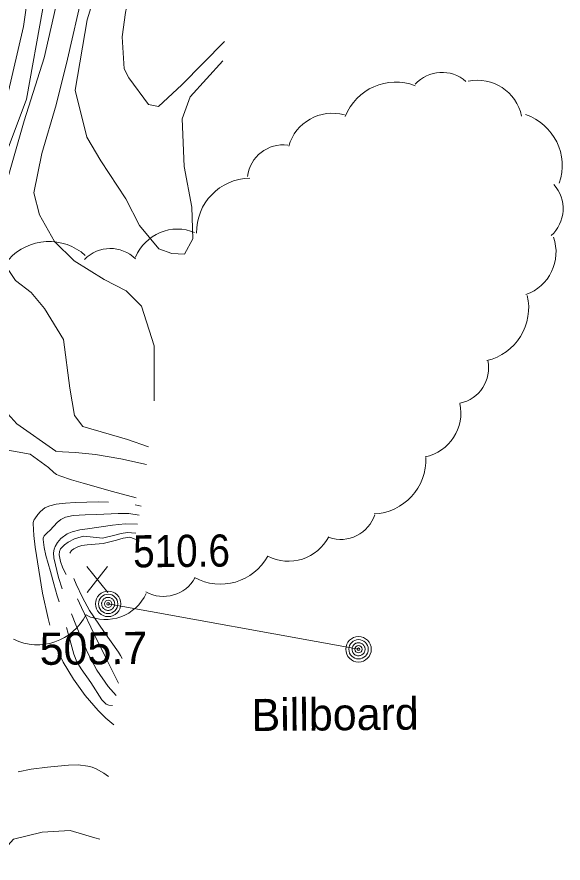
# Model space of a CAD drawing. Extents: x 2361284 to 2366480, y 6976556 to 6985346.
# Drawn here: x 2364716.6 to 2364798.2, y 6978408.5 to 6978534.7 of the extents above; entities that cross this region are included whole.
import ezdxf

# ---------------------------------------------------------------- set-up
doc = ezdxf.new("R2010")
doc.units = 0
doc.header["$LTSCALE"] = 1.9
for name, color, linetype, lineweight in [('11', 7, 'Continuous', 13), ('12', 7, 'Continuous', 13), ('13', 7, 'Continuous', 13), ('16', 7, 'Continuous', 13), ('20', 7, 'Continuous', 13), ('22', 7, 'Continuous', 13), ('4', 7, 'Continuous', 13)]:
    doc.layers.add(name, color=color, linetype=linetype, lineweight=lineweight)

msp = doc.modelspace()

# ---------------------------------------------------------------- linework, layer by layer
at = {"layer": '11'}
msp.add_line((2364767.64, 6978440.362), (2364730.263, 6978447.136), dxfattribs=at)
at = {"layer": '12'}
for p, q in [((2364730.202, 6978448.849), (2364727.085, 6978452.7)), ((2364727.122, 6978448.82), (2364730.165, 6978452.729))]:
    msp.add_line(p, q, dxfattribs=at)
for points in [[(2364750.359, 6978632.669), (2364748.604, 6978629.042), (2364742.684, 6978613.334), (2364736.777, 6978599.207), (2364731.034, 6978581.641), (2364723.423, 6978559.607), (2364719.142, 6978543.817), (2364717.643, 6978533.281), (2364713.596, 6978516.152), (2364707.687, 6978496.026), (2364707.136, 6978484.479), (2364708.384, 6978478.43), (2364710.15, 6978472.516), (2364714.733, 6978470.18), (2364718.619, 6978469.487), (2364721.379, 6978467.494)], [(2364744.069, 6978574.975), (2364740.975, 6978564.775), (2364736.359, 6978548.471), (2364733.744, 6978539.585), (2364732.854, 6978535.386), (2364732.338, 6978531.741), (2364732.664, 6978526.975), (2364733.366, 6978525.641), (2364736.304, 6978521.639), (2364737.777, 6978521.363), (2364741.247, 6978524.596), (2364747.606, 6978531.046)]]:
    msp.add_lwpolyline(points, dxfattribs=at)
at = {"layer": '13'}
for points in [[(2364752.059, 6978630.645), (2364748.887, 6978623.483), (2364744.822, 6978611.455), (2364740.85, 6978598.896), (2364733.997, 6978583.46), (2364728.05, 6978566.202), (2364723.391, 6978550.377), (2364720.497, 6978535.998), (2364718.096, 6978522.456), (2364713.324, 6978509.969), (2364711.568, 6978503.302), (2364710.216, 6978498.26), (2364709.669, 6978494.723), (2364710.081, 6978492.397), (2364711.554, 6978486.861), (2364712.256, 6978483.538), (2364713.878, 6978476.983), (2364716.627, 6978473.979), (2364722.436, 6978469.904)], [(2364740.908, 6978574.955), (2364740.363, 6978573.32), (2364735.089, 6978558.978), (2364730.529, 6978545.375), (2364727.134, 6978534.261), (2364725.363, 6978523.795), (2364727.07, 6978516.78), (2364729.194, 6978513.23), (2364732.918, 6978507.585), (2364734.946, 6978503.594), (2364737.819, 6978500.121), (2364739.786, 6978499.401), (2364741.637, 6978499.299), (2364742.915, 6978501.63), (2364742.741, 6978506.338), (2364741.623, 6978512.378), (2364741.295, 6978519.506), (2364742.52, 6978522.772), (2364747.363, 6978528.183)], [(2364726.436, 6978538.225), (2364724.2, 6978528.403), (2364722.514, 6978521.578), (2364720.342, 6978514.346), (2364719.148, 6978508.454), (2364720.009, 6978505.172), (2364722.268, 6978501.213), (2364725.205, 6978498.342), (2364729.672, 6978495.525), (2364732.928, 6978493.855), (2364735.23, 6978491.556), (2364737.107, 6978485.654), (2364737.155, 6978477.454)], [(2364722.387, 6978536.026), (2364720.717, 6978528.62), (2364717.737, 6978519.192), (2364715.249, 6978510.497), (2364714.431, 6978507.179), (2364713.441, 6978503.01), (2364714.618, 6978498.072), (2364716.423, 6978495.409), (2364718.75, 6978493.58), (2364720.783, 6978491.209), (2364723.607, 6978486.586), (2364724.546, 6978479.324), (2364725.251, 6978475.222), (2364726.471, 6978473.592), (2364733.129, 6978471.664), (2364736.29, 6978470.545)], [(2364728.996, 6978412.023), (2364728.264, 6978412.246), (2364724.604, 6978413.342), (2364720.426, 6978413.062), (2364716.146, 6978412.021), (2364714.145, 6978409.782), (2364712.098, 6978404.431), (2364709.934, 6978397.481), (2364707.365, 6978390.986), (2364702.271, 6978384.017), (2364696.655, 6978375.143), (2364695.702, 6978372.639), (2364695.939, 6978367.306), (2364699.956, 6978361.393), (2364705.109, 6978357.943), (2364707.713, 6978355.528), (2364708.332, 6978354.553), (2364710.337, 6978352.952), (2364707.952, 6978350.35), (2364703.557, 6978348.688), (2364701.789, 6978346.451), (2364699.834, 6978343.551), (2364700.077, 6978342.414), (2364702.588, 6978341.288)]]:
    msp.add_lwpolyline(points, dxfattribs=at)
at = {"layer": '16'}
for centre, radius, start, end in [((2364780.076, 6978521.069), 5.381, 48.10943, 138.10943), ((2364773.188, 6978516.923), 8.076, 68.82502, 158.82502), ((2364785.38, 6978518.548), 6.734, 11.77598, 101.77598), ((2364763.708, 6978513.608), 6.734, 74.37675, 164.37675), ((2364789.968, 6978512.504), 8.076, 341.1653, 71.1653), ((2364756.41, 6978510.257), 5.381, 82.90169, 172.90169), ((2364751.536, 6978502.59), 8.076, 91.03314, 181.03314), ((2364792.791, 6978506.088), 5.381, 312.01795, 42.01795), ((2364740.595, 6978496.326), 6.734, 67.5884, 157.5884), ((2364790.387, 6978499.647), 6.734, 289.2099, 19.2099), ((2364721.427, 6978493.139), 8.076, 47.96859, 137.96859), ((2364730.585, 6978494.779), 5.381, 45.64299, 135.64299), ((2364784.964, 6978491.31), 8.076, 283.21455, 13.21455), ((2364781.664, 6978482.337), 5.381, 281.98727, 11.98727), ((2364776.185, 6978475.652), 6.734, 281.98727, 11.98727), ((2364769.598, 6978468.624), 8.076, 272.63358, 2.63358), ((2364764.967, 6978462.133), 5.381, 251.57895, 341.57895), ((2364757.204, 6978460.231), 6.734, 242.72757, 332.72757), ((2364747.038, 6978458.16), 8.076, 241.08099, 331.08099), ((2364738.511, 6978453.631), 5.381, 241.08099, 331.08099), ((2364729.854, 6978451.537), 6.734, 245.03229, 335.03229), ((2364719.702, 6978449.102), 8.076, 243.95518, 333.95518)]:
    msp.add_arc(centre, radius, start, end, dxfattribs=at)
at = {"layer": '20'}
msp.add_line((2364734.282, 6978461.916), (2364735.194, 6978461.695), dxfattribs=at)
for points in [[(2364722.456, 6978469.864), (2364725.408, 6978469.722), (2364728.351, 6978469.42), (2364732.177, 6978468.796), (2364735.965, 6978467.942)], [(2364721.582, 6978443.963), (2364721.303, 6978444.941), (2364720.477, 6978448.733), (2364719.893, 6978452.149), (2364719.372, 6978455.574), (2364719.165, 6978457.342), (2364719.058, 6978459.111), (2364719.076, 6978459.301), (2364719.105, 6978459.432), (2364719.183, 6978459.632), (2364719.301, 6978459.833), (2364719.764, 6978460.488), (2364720.15, 6978460.922), (2364720.806, 6978461.448), (2364721.174, 6978461.641), (2364721.573, 6978461.785), (2364722.511, 6978462.004), (2364723.919, 6978462.177), (2364725.329, 6978462.251), (2364728.828, 6978462.354), (2364730.318, 6978462.308)], [(2364722.929, 6978447.426), (2364722.661, 6978448.334), (2364722.154, 6978450.139), (2364721.656, 6978451.945), (2364720.974, 6978454.339), (2364720.702, 6978455.537), (2364720.541, 6978456.725), (2364720.559, 6978456.935), (2364720.716, 6978457.267), (2364721.141, 6978457.721), (2364721.607, 6978458.155), (2364722.647, 6978459.285), (2364723.212, 6978459.751), (2364723.879, 6978460.067), (2364725.047, 6978460.328), (2364726.816, 6978460.445), (2364728.586, 6978460.472), (2364731.744, 6978460.642), (2364733.325, 6978460.607), (2364734.897, 6978460.352)], [(2364723.411, 6978449.381), (2364722.855, 6978451.077), (2364722.157, 6978454.01), (2364722.12, 6978454.74), (2364722.215, 6978455.291), (2364722.361, 6978455.692), (2364722.705, 6978456.296), (2364723.2, 6978456.87), (2364724.153, 6978457.599), (2364724.89, 6978457.906), (2364726.017, 6978458.167), (2364727.186, 6978458.328), (2364730.911, 6978458.904), (2364732.779, 6978459.062), (2364734.64, 6978459.019)], [(2364723.971, 6978451.497), (2364723.501, 6978452.473), (2364723.132, 6978453.48), (2364722.932, 6978454.478), (2364722.988, 6978454.948), (2364723.164, 6978455.34), (2364723.728, 6978455.955), (2364724.295, 6978456.351), (2364725.26, 6978456.83), (2364726.217, 6978457.159), (2364726.616, 6978457.223), (2364729.409, 6978456.949), (2364731.265, 6978457.407), (2364732.203, 6978457.646), (2364733.142, 6978457.765), (2364733.762, 6978457.731), (2364734.382, 6978457.697)], [(2364731.785, 6978435.281), (2364731.642, 6978435.58), (2364731.49, 6978435.878), (2364729.797, 6978439.292), (2364728.114, 6978442.716), (2364726.268, 6978446.588), (2364725.665, 6978447.872)], [(2364731.473, 6978433.448), (2364730.24, 6978434.816), (2364728.557, 6978437.23), (2364727.181, 6978439.877), (2364725.432, 6978443.99), (2364724.797, 6978445.634)], [(2364730.897, 6978431.982), (2364730.366, 6978431.997), (2364729.945, 6978432.183), (2364729.299, 6978432.797), (2364727.664, 6978435.412), (2364726.214, 6978437.458), (2364725.604, 6978438.512), (2364725.143, 6978439.648), (2364724.543, 6978441.822), (2364724.056, 6978443.587)], [(2364731.124, 6978429.064), (2364729.894, 6978430.103), (2364728.764, 6978431.232), (2364726.832, 6978433.474), (2364725.079, 6978435.877), (2364723.545, 6978438.453), (2364722.912, 6978439.797), (2364722.779, 6978440.146)]]:
    msp.add_lwpolyline(points, dxfattribs=at)
at = {"layer": '22'}
for points in [[(2364721.379, 6978467.494), (2364722.146, 6978466.751), (2364722.559, 6978466.445), (2364723.031, 6978466.219), (2364724.776, 6978465.666), (2364726.531, 6978465.162), (2364730.913, 6978463.924), (2364734.462, 6978462.948)], [(2364724.52, 6978454.723), (2364724.807, 6978455.076), (2364725.134, 6978455.339), (2364725.712, 6978455.634), (2364726.32, 6978455.83), (2364727.119, 6978455.958), (2364729.517, 6978456.13), (2364731.512, 6978456.649), (2364732.51, 6978456.919), (2364733.498, 6978457.068), (2364733.618, 6978457.059), (2364733.819, 6978456.991), (2364734.13, 6978456.844), (2364734.281, 6978456.776), (2364734.441, 6978456.747)], [(2364732.37, 6978438.987), (2364732.086, 6978439.454), (2364731.791, 6978439.911), (2364729.642, 6978443.021), (2364727.472, 6978446.129), (2364726.423, 6978448.08), (2364725.504, 6978450.101), (2364725.136, 6978450.927)], [(2364730.337, 6978421.386), (2364729.612, 6978421.899), (2364728.476, 6978422.528), (2364727.864, 6978422.762), (2364727.232, 6978422.936), (2364725.781, 6978423.122), (2364724.341, 6978423.089), (2364722.772, 6978422.944), (2364721.214, 6978422.769), (2364718.776, 6978422.476), (2364716.81, 6978422.097)]]:
    msp.add_lwpolyline(points, dxfattribs=at)
at = {"layer": '4'}
for centre, radius in [((2364730.263, 6978447.136), 1.9), ((2364730.263, 6978447.136), 1.442), ((2364730.263, 6978447.136), 0.539), ((2364730.263, 6978447.136), 0.192), ((2364767.64, 6978440.362), 1.9), ((2364767.64, 6978440.362), 1.442), ((2364767.64, 6978440.362), 0.539), ((2364767.64, 6978440.362), 0.192)]:
    msp.add_circle(centre, radius, dxfattribs=at)
for centre, start, end in [((2364730.263, 6978447.136), 175.14463, 186.39466), ((2364730.263, 6978447.136), 163.89671, 175.14675), ((2364730.263, 6978447.136), 186.39597, 197.64601), ((2364730.263, 6978447.136), 152.64729, 163.89733), ((2364730.263, 6978447.136), 141.39537, 152.6454), ((2364730.263, 6978447.136), 130.14764, 141.39767), ((2364730.263, 6978447.136), 118.89707, 130.14711), ((2364730.263, 6978447.136), 107.64524, 118.89528), ((2364730.263, 6978447.136), 96.39711, 107.64715), ((2364730.263, 6978447.136), 85.147, 96.39703), ((2364730.263, 6978447.136), 73.89671, 85.14675), ((2364730.263, 6978447.136), 62.64376, 73.89379), ((2364730.263, 6978447.136), 51.3993, 62.64933), ((2364730.263, 6978447.136), 40.14515, 51.39518), ((2364730.263, 6978447.136), 28.89494, 40.14497), ((2364730.263, 6978447.136), 17.6494, 28.89944), ((2364730.263, 6978447.136), 6.39598, 17.64601), ((2364730.263, 6978447.136), 343.8967, 355.14674), ((2364730.263, 6978447.136), 355.14405, 6.39409), ((2364730.263, 6978447.136), 197.64774, 208.89778), ((2364730.263, 6978447.136), 208.89706, 220.14709), ((2364730.263, 6978447.136), 220.14515, 231.39518), ((2364730.263, 6978447.136), 231.39653, 242.64656), ((2364730.263, 6978447.136), 242.6467, 253.89673), ((2364730.263, 6978447.136), 253.89671, 265.14675), ((2364730.263, 6978447.136), 265.147, 276.39703), ((2364730.263, 6978447.136), 276.39711, 287.64715), ((2364730.263, 6978447.136), 287.64524, 298.89527), ((2364730.263, 6978447.136), 298.89494, 310.14497), ((2364730.263, 6978447.136), 310.14764, 321.39767), ((2364730.263, 6978447.136), 321.39653, 332.64656), ((2364730.263, 6978447.136), 332.64729, 343.89733), ((2364767.64, 6978440.362), 152.64729, 163.89733), ((2364767.64, 6978440.362), 141.39537, 152.6454), ((2364767.64, 6978440.362), 130.14764, 141.39767), ((2364767.64, 6978440.362), 118.89707, 130.14711), ((2364767.64, 6978440.362), 107.64524, 118.89528), ((2364767.64, 6978440.362), 96.39711, 107.64715), ((2364767.64, 6978440.362), 85.147, 96.39703), ((2364767.64, 6978440.362), 73.89671, 85.14675), ((2364767.64, 6978440.362), 62.64376, 73.89379), ((2364767.64, 6978440.362), 51.3993, 62.64933), ((2364767.64, 6978440.362), 40.14515, 51.39518), ((2364767.64, 6978440.362), 28.89494, 40.14497), ((2364767.64, 6978440.362), 17.6494, 28.89944), ((2364767.64, 6978440.362), 175.14463, 186.39466), ((2364767.64, 6978440.362), 163.89671, 175.14675), ((2364767.64, 6978440.362), 186.39597, 197.64601), ((2364767.64, 6978440.362), 197.64774, 208.89778), ((2364767.64, 6978440.362), 208.89706, 220.14709), ((2364767.64, 6978440.362), 220.14515, 231.39518), ((2364767.64, 6978440.362), 231.39653, 242.64656), ((2364767.64, 6978440.362), 242.6467, 253.89673), ((2364767.64, 6978440.362), 287.64524, 298.89527), ((2364767.64, 6978440.362), 298.89494, 310.14497), ((2364767.64, 6978440.362), 310.14764, 321.39767), ((2364767.64, 6978440.362), 321.39653, 332.64656), ((2364767.64, 6978440.362), 332.64729, 343.89733), ((2364767.64, 6978440.362), 6.39598, 17.64601), ((2364767.64, 6978440.362), 343.8967, 355.14674), ((2364767.64, 6978440.362), 355.14405, 6.39409), ((2364767.64, 6978440.362), 253.89671, 265.14675), ((2364767.64, 6978440.362), 265.147, 276.39703), ((2364767.64, 6978440.362), 276.39711, 287.64715)]:
    msp.add_arc(centre, 0.973, start, end, dxfattribs=at)

# ---------------------------------------------------------------- texts
at = {"layer": '11'}
msp.add_text('Billboard', height=4.799, rotation=0.545, dxfattribs=at).set_placement((2364751.684, 6978428.149))
at = {"layer": '12', "width": 0.9}
msp.add_text('510.6', height=4.799, rotation=0.545, dxfattribs=at).set_placement((2364734.011, 6978452.573))
at = {"layer": '12'}
msp.add_text('505.7', height=4.799, rotation=0.545, dxfattribs=at).set_placement((2364720.058, 6978438.03))

doc.saveas('drawing.dxf')
